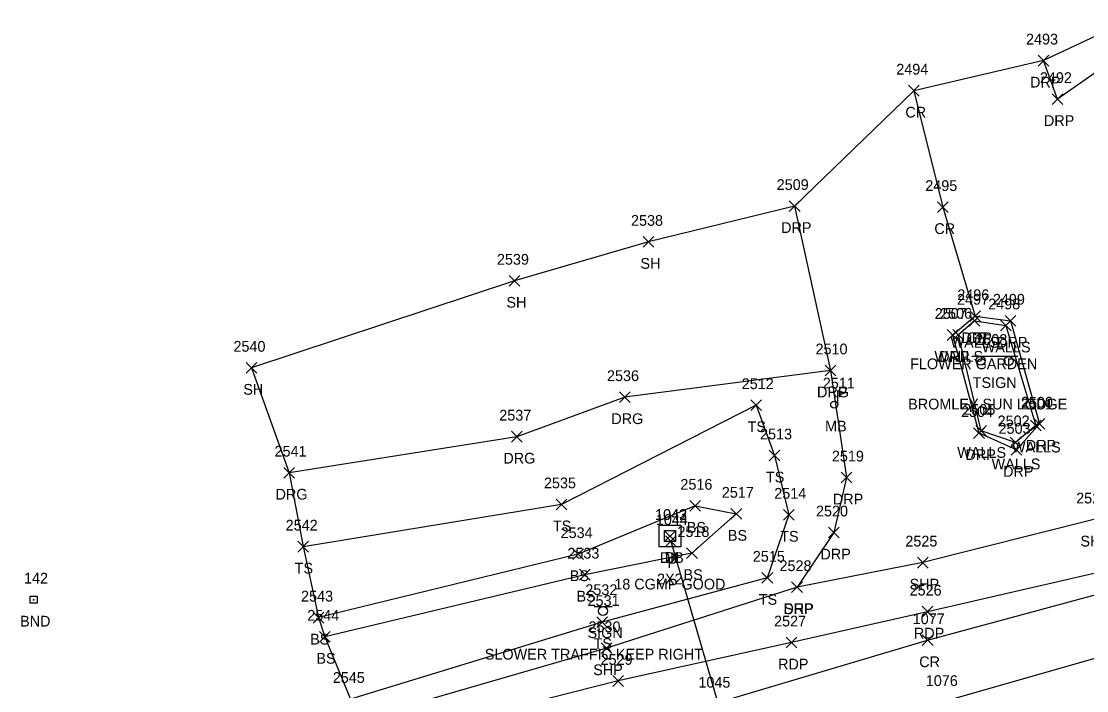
# Model space of a CAD drawing. Extents: x 49137 to 50946, y 9590 to 10709.
# Drawn here: x 49570.6 to 49768.6, y 9959 to 10083.5 of the extents above; entities that cross this region are included whole.
import ezdxf

# ---------------------------------------------------------------- set-up
doc = ezdxf.new("R2010")
doc.units = 0
for name, color, linetype in [('D_A', 7, 'Continuous'), ('D_C', 7, 'Continuous'), ('D_I', 7, 'Continuous'), ('D_TIC', 7, 'Continuous'), ('DCP', 7, 'Continuous'), ('DS', 7, 'Continuous'), ('L_A', 7, 'Continuous'), ('L_C', 7, 'Continuous'), ('L_I', 7, 'Continuous'), ('L_TIC', 7, 'Continuous'), ('LELB', 7, 'Continuous'), ('LMB', 7, 'Continuous'), ('LSOGP', 7, 'Continuous'), ('LWS', 7, 'Continuous'), ('M_A', 7, 'Continuous'), ('M_I', 7, 'Continuous'), ('MHBP', 7, 'Continuous'), ('P_A', 7, 'Continuous'), ('P_I', 7, 'Continuous'), ('P_TIC', 7, 'Continuous'), ('PET', 7, 'Continuous'), ('PRC', 7, 'Continuous'), ('PSP', 7, 'Continuous'), ('R_A', 7, 'Continuous'), ('R_I', 7, 'Continuous'), ('R_TIC', 7, 'Continuous'), ('RDG', 7, 'Continuous'), ('RDP', 7, 'Continuous'), ('S_A', 7, 'Continuous'), ('S_C', 7, 'Continuous'), ('S_I', 7, 'Continuous'), ('SSGN', 7, 'Continuous')]:
    doc.layers.add(name, color=color, linetype=linetype)

msp = doc.modelspace()

# ---------------------------------------------------------------- linework, layer by layer
at = {"layer": 'D_TIC'}
for points in [[(49690.14, 9986.76), (49692.14, 9988.76)], [(49692.14, 9986.76), (49690.14, 9988.76)], [(49690.29, 9985.82), (49692.29, 9987.82)], [(49692.29, 9985.82), (49690.29, 9987.82)]]:
    msp.add_lwpolyline(points, dxfattribs=at)
at = {"layer": 'DCP'}
msp.add_lwpolyline([(49691.29, 9986.82), (49735.05, 9836.12)], dxfattribs=at)
at = {"layer": 'DS'}
for p, q in [((49689.15, 9989.77), (49693.15, 9989.77)), ((49689.15, 9985.77), (49689.15, 9989.77)), ((49690.15, 9986.77), (49690.15, 9988.77)), ((49690.15, 9988.77), (49692.15, 9988.77)), ((49692.15, 9988.77), (49692.15, 9986.77)), ((49693.15, 9989.77), (49693.15, 9985.77)), ((49692.15, 9986.77), (49690.15, 9986.77)), ((49691.16, 9987.77), (49691.16, 9987.77)), ((49691.16, 9987.77), (49691.16, 9987.77)), ((49693.15, 9985.77), (49689.15, 9985.77))]:
    msp.add_line(p, q, dxfattribs=at)
at = {"layer": 'L_TIC'}
for points in [[(49686.16, 10041.48), (49688.16, 10043.48)], [(49688.16, 10041.48), (49686.16, 10043.48)], [(49661.24, 10034.24), (49663.24, 10036.24)], [(49663.24, 10034.24), (49661.24, 10036.24)], [(49746.76, 10026.8), (49748.76, 10028.8)], [(49748.76, 10026.8), (49746.76, 10028.8)], [(49746.76, 10026.8), (49748.76, 10028.8)], [(49748.76, 10026.8), (49746.76, 10028.8)], [(49752.56, 10025.93), (49754.56, 10027.93)], [(49754.56, 10025.93), (49752.56, 10027.93)], [(49743.75, 10024.19), (49745.75, 10026.19)], [(49745.75, 10024.19), (49743.75, 10026.19)], [(49743.75, 10024.19), (49745.75, 10026.19)], [(49745.75, 10024.19), (49743.75, 10026.19)], [(49612.33, 10018.05), (49614.33, 10020.05)], [(49614.33, 10018.05), (49612.33, 10020.05)], [(49706.17, 10011.1), (49708.17, 10013.1)], [(49708.17, 10011.1), (49706.17, 10013.1)], [(49706.17, 10011.1), (49708.17, 10013.1)], [(49708.17, 10011.1), (49706.17, 10013.1)], [(49748.01, 10006.31), (49750.01, 10008.31)], [(49750.01, 10006.31), (49748.01, 10008.31)], [(49758.16, 10007.31), (49760.16, 10009.31)], [(49760.16, 10007.31), (49758.16, 10009.31)], [(49754.39, 10004.18), (49756.39, 10006.18)], [(49756.39, 10004.18), (49754.39, 10006.18)], [(49709.58, 10001.74), (49711.58, 10003.74)], [(49711.58, 10001.74), (49709.58, 10003.74)], [(49669.97, 9992.64), (49671.97, 9994.64)], [(49671.97, 9992.64), (49669.97, 9994.64)], [(49694.83, 9992.38), (49696.83, 9994.38)], [(49696.83, 9992.38), (49694.83, 9994.38)], [(49694.83, 9992.38), (49696.83, 9994.38)], [(49696.83, 9992.38), (49694.83, 9994.38)], [(49702.47, 9990.89), (49704.47, 9992.89)], [(49704.47, 9990.89), (49702.47, 9992.89)], [(49712.22, 9990.71), (49714.22, 9992.71)], [(49714.22, 9990.71), (49712.22, 9992.71)], [(49621.96, 9984.78), (49623.96, 9986.78)], [(49623.96, 9984.78), (49621.96, 9986.78)], [(49673.07, 9983.38), (49675.07, 9985.38)], [(49675.07, 9983.38), (49673.07, 9985.38)], [(49694.23, 9983.58), (49696.23, 9985.58)], [(49696.23, 9983.58), (49694.23, 9985.58)], [(49674.33, 9979.57), (49676.33, 9981.57)], [(49676.33, 9979.57), (49674.33, 9981.57)], [(49708.24, 9978.98), (49710.24, 9980.98)], [(49710.24, 9978.98), (49708.24, 9980.98)], [(49624.82, 9971.58), (49626.82, 9973.58)], [(49626.82, 9971.58), (49624.82, 9973.58)], [(49677.52, 9970.76), (49679.52, 9972.76)], [(49679.52, 9970.76), (49677.52, 9972.76)], [(49625.97, 9968.01), (49627.97, 9970.01)], [(49627.97, 9968.01), (49625.97, 9970.01)]]:
    msp.add_lwpolyline(points, dxfattribs=at)
at = {"layer": 'LELB'}
for points in [[(49707.17, 10012.1), (49670.97, 9993.64), (49622.96, 9985.78)], [(49707.17, 10012.1), (49710.58, 10002.74), (49713.22, 9991.71), (49709.24, 9979.98), (49678.52, 9971.76), (49631.72, 9957.44)], [(49695.83, 9993.38), (49674.07, 9984.38), (49625.82, 9972.58)], [(49695.83, 9993.38), (49703.47, 9991.89), (49695.23, 9984.58), (49675.33, 9980.57), (49626.97, 9969.01)]]:
    msp.add_lwpolyline(points, dxfattribs=at)
at = {"layer": 'LMB'}
for p, q in [((49722.33, 10014.81), (49723.62, 10014.43)), ((49722.33, 10012.22), (49722.33, 10014.81)), ((49722.33, 10013.91), (49723.61, 10014.42)), ((49721.68, 10012.21), (49721.68, 10012.21))]:
    msp.add_line(p, q, dxfattribs=at)
msp.add_circle((49721.68, 10012.21), 0.656, dxfattribs=at)
at = {"layer": 'LSOGP'}
msp.add_lwpolyline([(49776.2, 10083.52), (49760.59, 10076.2), (49736.46, 10070.61), (49714.32, 10049.15), (49687.16, 10042.49), (49662.24, 10035.25), (49613.34, 10019.05), (49620.33, 9999.55), (49622.96, 9985.79), (49625.81, 9972.58), (49626.96, 9969.01), (49631.72, 9957.44)], dxfattribs=at)
at = {"layer": 'LWS'}
for points in [[(49747.76, 10027.8), (49753.56, 10026.93), (49759.16, 10008.31), (49755.39, 10005.18), (49749.01, 10007.31), (49744.75, 10025.19)], [(49747.76, 10027.8), (49744.75, 10025.19)]]:
    msp.add_lwpolyline(points, dxfattribs=at)
at = {"layer": 'MHBP'}
msp.add_lwpolyline([(49572.22, 9976.55), (49573.47, 9976.55), (49573.47, 9975.3), (49572.22, 9975.3)], close=True, dxfattribs=at)
msp.add_circle((49572.85, 9975.92), 0.0833, dxfattribs=at)
at = {"layer": 'P_TIC'}
for points in [[(49735.47, 10069.61), (49737.47, 10071.61)], [(49737.47, 10069.61), (49735.47, 10071.61)], [(49740.86, 10047.95), (49742.86, 10049.95)], [(49742.86, 10047.95), (49740.86, 10049.95)], [(49746.87, 10027.65), (49748.87, 10029.65)], [(49748.87, 10027.65), (49746.87, 10029.65)], [(49737.16, 9981.81), (49739.16, 9983.81)], [(49739.16, 9981.81), (49737.16, 9983.81)], [(49713.76, 9977.24), (49715.76, 9979.24)], [(49715.76, 9977.24), (49713.76, 9979.24)], [(49738, 9972.69), (49740, 9974.69)], [(49740, 9972.69), (49738, 9974.69)], [(49712.75, 9966.94), (49714.75, 9968.94)], [(49714.75, 9966.94), (49712.75, 9968.94)], [(49738.04, 9967.37), (49740.04, 9969.37)], [(49740.04, 9967.37), (49738.04, 9969.37)], [(49678.34, 9965.88), (49680.34, 9967.88)], [(49680.34, 9965.88), (49678.34, 9967.88)], [(49680.51, 9959.8), (49682.51, 9961.8)], [(49682.51, 9959.8), (49680.51, 9961.8)]]:
    msp.add_lwpolyline(points, dxfattribs=at)
at = {"layer": 'PET'}
msp.add_lwpolyline([(49773.46, 9981.58), (49739, 9973.69), (49713.75, 9967.94), (49681.51, 9960.8), (49634.84, 9948.96)], dxfattribs=at)
at = {"layer": 'PRC'}
for points in [[(49736.47, 10070.61), (49741.86, 10048.95), (49747.87, 10028.65)], [(49635.51, 9938.51), (49665.25, 9946.57), (49699.21, 9956.56), (49739.04, 9968.37), (49782.75, 9980.26), (49832.37, 9994.06), (49891.41, 10012.39)], [(49638.31, 9927.11), (49668.24, 9935.56), (49702.01, 9945.71), (49741.53, 9956.86), (49785.57, 9969.42)]]:
    msp.add_lwpolyline(points, dxfattribs=at)
at = {"layer": 'PSP'}
msp.add_lwpolyline([(49769.91, 9990.82), (49738.16, 9982.81), (49714.76, 9978.24), (49679.34, 9966.88), (49632.26, 9953.25)], dxfattribs=at)
at = {"layer": 'R_TIC'}
for points in [[(49759.59, 10075.2), (49761.59, 10077.2)], [(49761.59, 10075.2), (49759.59, 10077.2)], [(49762.17, 10068.04), (49764.17, 10070.04)], [(49764.17, 10068.04), (49762.17, 10070.04)], [(49713.32, 10048.14), (49715.32, 10050.14)], [(49715.32, 10048.14), (49713.32, 10050.14)], [(49746.87, 10027.65), (49748.87, 10029.65)], [(49748.87, 10027.65), (49746.87, 10029.65)], [(49746.87, 10027.65), (49748.87, 10029.65)], [(49748.87, 10027.65), (49746.87, 10029.65)], [(49753.44, 10026.81), (49755.44, 10028.81)], [(49755.44, 10026.81), (49753.44, 10028.81)], [(49742.7, 10024.16), (49744.7, 10026.16)], [(49744.7, 10024.16), (49742.7, 10026.16)], [(49742.7, 10024.16), (49744.7, 10026.16)], [(49744.7, 10024.16), (49742.7, 10026.16)], [(49719.98, 10017.56), (49721.98, 10019.56)], [(49721.98, 10017.56), (49719.98, 10019.56)], [(49719.98, 10017.56), (49721.98, 10019.56)], [(49721.98, 10017.56), (49719.98, 10019.56)], [(49681.75, 10012.59), (49683.75, 10014.59)], [(49683.75, 10012.59), (49681.75, 10014.59)], [(49747.59, 10005.91), (49749.59, 10007.91)], [(49749.59, 10005.91), (49747.59, 10007.91)], [(49758.81, 10007.65), (49760.81, 10009.65)], [(49760.81, 10007.65), (49758.81, 10009.65)], [(49661.67, 10005.24), (49663.67, 10007.24)], [(49663.67, 10005.24), (49661.67, 10007.24)], [(49754.57, 10002.78), (49756.57, 10004.78)], [(49756.57, 10002.78), (49754.57, 10004.78)], [(49619.33, 9998.54), (49621.33, 10000.54)], [(49621.33, 9998.54), (49619.33, 10000.54)], [(49722.94, 9997.63), (49724.94, 9999.63)], [(49724.94, 9997.63), (49722.94, 9999.63)], [(49720.62, 9987.41), (49722.62, 9989.41)], [(49722.62, 9987.41), (49720.62, 9989.41)], [(49713.76, 9977.24), (49715.76, 9979.24)], [(49715.76, 9977.24), (49713.76, 9979.24)]]:
    msp.add_lwpolyline(points, dxfattribs=at)
at = {"layer": 'RDG'}
msp.add_lwpolyline([(49720.98, 10018.56), (49682.75, 10013.59), (49662.67, 10006.24), (49620.33, 9999.54)], dxfattribs=at)
at = {"layer": 'RDP'}
for points in [[(49776.21, 10083.52), (49771.42, 10074.83), (49763.17, 10069.04), (49760.59, 10076.2)], [(49714.32, 10049.14), (49720.98, 10018.56), (49723.94, 9998.63), (49721.62, 9988.41), (49714.76, 9978.24)], [(49747.87, 10028.65), (49754.44, 10027.81), (49759.81, 10008.65), (49755.57, 10003.78), (49748.59, 10006.91), (49743.7, 10025.16)], [(49747.87, 10028.65), (49743.7, 10025.16)]]:
    msp.add_lwpolyline(points, dxfattribs=at)
at = {"layer": 'SSGN'}
for p, q in [((49747.23, 10021.23), (49755.82, 10021.23)), ((49751.25, 10020.33), (49751.25, 10020.33)), ((49677.04, 9974.64), (49680.37, 9974.64)), ((49678.69, 9973.81), (49678.69, 9973.81))]:
    msp.add_line(p, q, dxfattribs=at)
for centre in [(49748.89, 10020.4), (49754.1, 10020.33), (49678.69, 9973.81)]:
    msp.add_circle(centre, 0.833, dxfattribs=at)

# ---------------------------------------------------------------- texts
at = {"layer": 'D_A'}
for s, p in [('DIB', (49689.24, 9982.76)), ('DI', (49690.21, 9982.77)), ('P', (49690.66, 9981.82))]:
    msp.add_text(s, height=2, dxfattribs=at).set_placement(p)
at = {"layer": 'D_C'}
for s, p in [('2X2', (49688.73, 9978.77)), ('18 CGMP GOOD', (49680.79, 9977.82))]:
    msp.add_text(s, height=2, dxfattribs=at).set_placement(p)
at = {"layer": 'D_I'}
for s, p in [('1043', (49688.36, 9990.76)), ('1042', (49688.39, 9990.77)), ('1044', (49688.51, 9989.82))]:
    msp.add_text(s, height=2, dxfattribs=at).set_placement(p)
at = {"layer": 'L_A'}
for s, p in [('SH', (49685.65, 10037.48)), ('SH', (49660.73, 10030.24)), ('WALLS', (49743.3, 10022.8)), ('WALLS', (49743.3, 10022.8)), ('WALLS', (49749.11, 10021.93)), ('WALLS', (49740.3, 10020.19)), ('WALLS', (49740.3, 10020.19)), ('SH', (49611.82, 10014.05)), ('TS', (49705.58, 10007.1)), ('TS', (49705.58, 10007.1)), ('MB', (49719.98, 10007.21)), ('WALLS', (49744.55, 10002.31)), ('WALLS', (49754.71, 10003.31)), ('WALLS', (49750.93, 10000.18)), ('TS', (49708.99, 9997.74)), ('TS', (49669.38, 9988.64)), ('BS', (49694.27, 9988.38)), ('BS', (49694.27, 9988.38)), ('BS', (49701.91, 9986.89)), ('TS', (49711.63, 9986.71)), ('TS', (49621.37, 9980.78)), ('BS', (49672.51, 9979.38)), ('BS', (49693.67, 9979.58)), ('BS', (49673.77, 9975.57)), ('TS', (49707.65, 9974.98)), ('BS', (49624.26, 9967.58)), ('TS', (49676.93, 9966.76)), ('BS', (49625.41, 9964.01))]:
    msp.add_text(s, height=2, dxfattribs=at).set_placement(p)
at = {"layer": 'L_C'}
msp.add_text('FLOWER GARDEN', height=2, dxfattribs=at).set_placement((49735.79, 10018.8))
msp.add_text('FLOWER GARDEN', height=2, dxfattribs=at).set_placement((49735.79, 10018.8))
at = {"layer": 'L_I'}
for s, p in [('2538', (49683.9, 10045.48)), ('2539', (49658.97, 10038.24)), ('2497', (49744.5, 10030.8)), ('2497', (49744.5, 10030.8)), ('2498', (49750.3, 10029.93)), ('2506', (49741.36, 10028.19)), ('2506', (49741.36, 10028.19)), ('2540', (49609.99, 10022.05)), ('2512', (49704.48, 10015.1)), ('2512', (49704.48, 10015.1)), ('2511', (49719.55, 10015.21)), ('2505', (49745.67, 10010.31)), ('2501', (49756.39, 10011.31)), ('2502', (49752.05, 10008.18)), ('2513', (49707.89, 10005.74)), ('2535', (49667.71, 9996.64)), ('2516', (49693.08, 9996.38)), ('2516', (49693.08, 9996.38)), ('2517', (49700.78, 9994.89)), ('2514', (49710.53, 9994.71)), ('2542', (49619.7, 9988.78)), ('2534', (49670.81, 9987.38)), ('2518', (49692.53, 9987.58)), ('2533', (49672.07, 9983.57)), ('2515', (49706.54, 9982.98)), ('2543', (49622.56, 9975.58)), ('2531', (49675.82, 9974.76)), ('2544', (49623.71, 9972.01)), ('2545', (49628.46, 9960.44))]:
    msp.add_text(s, height=2, dxfattribs=at).set_placement(p)
at = {"layer": 'M_A'}
msp.add_text('BND', height=2, dxfattribs=at).set_placement((49570.33, 9970.92))
at = {"layer": 'M_I'}
msp.add_text('142', height=2, dxfattribs=at).set_placement((49571.05, 9978.92))
at = {"layer": 'P_A'}
for s, p in [('CR', (49734.9, 10065.61)), ('CR', (49740.29, 10043.95)), ('CR', (49746.3, 10023.65)), ('SHP', (49767.44, 9985.82)), ('SHP', (49735.69, 9977.81)), ('SHP', (49712.29, 9973.24)), ('RDP', (49736.49, 9968.69)), ('RDP', (49711.23, 9962.94)), ('CR', (49737.48, 9963.37)), ('SHP', (49676.87, 9961.88))]:
    msp.add_text(s, height=2, dxfattribs=at).set_placement(p)
at = {"layer": 'P_I'}
for s, p in [('2494', (49733.21, 10073.61)), ('2495', (49738.6, 10051.95)), ('2496', (49744.55, 10031.65)), ('2524', (49766.65, 9993.82)), ('2525', (49734.9, 9985.81)), ('2528', (49711.5, 9981.24)), ('2526', (49735.69, 9976.69)), ('2527', (49710.49, 9970.94)), ('1077', (49736.27, 9971.37)), ('2530', (49675.99, 9969.88)), ('2529', (49678.24, 9963.8)), ('1045', (49696.43, 9959.56)), ('1076', (49738.7, 9959.86))]:
    msp.add_text(s, height=2, dxfattribs=at).set_placement(p)
at = {"layer": 'R_A'}
for s, p in [('DRP', (49758.08, 10071.2)), ('DRP', (49760.66, 10064.04)), ('DRP', (49711.81, 10044.14)), ('DRP', (49745.35, 10023.65)), ('DRP', (49745.35, 10023.65)), ('DRP', (49751.93, 10022.81)), ('DRP', (49741.19, 10020.16)), ('DRP', (49741.19, 10020.16)), ('DRG', (49718.47, 10013.56)), ('DRP', (49718.47, 10013.56)), ('DRG', (49680.23, 10008.59)), ('DRP', (49746.08, 10001.91)), ('DRP', (49757.29, 10003.65)), ('DRG', (49660.16, 10001.24)), ('DRP', (49753.06, 9998.78)), ('DRG', (49617.82, 9994.54)), ('DRP', (49721.43, 9993.63)), ('DRP', (49719.11, 9983.41)), ('DRP', (49712.24, 9973.24))]:
    msp.add_text(s, height=2, dxfattribs=at).set_placement(p)
at = {"layer": 'R_I'}
for s, p in [('2493', (49757.33, 10079.2)), ('2492', (49759.91, 10072.04)), ('2509', (49710.98, 10052.14)), ('2496', (49744.55, 10031.65)), ('2496', (49744.55, 10031.65)), ('2499', (49751.17, 10030.81)), ('2507', (49740.36, 10028.16)), ('2507', (49740.36, 10028.16)), ('2510', (49718.2, 10021.56)), ('2510', (49718.2, 10021.56)), ('2536', (49679.43, 10016.59)), ('2504', (49745.26, 10009.91)), ('2500', (49756.38, 10011.65)), ('2537', (49659.41, 10009.24)), ('2503', (49752.23, 10006.78)), ('2541', (49617.63, 10002.54)), ('2519', (49721.24, 10001.63)), ('2520', (49718.28, 9991.41)), ('2528', (49711.5, 9981.24))]:
    msp.add_text(s, height=2, dxfattribs=at).set_placement(p)
at = {"layer": 'S_A'}
for s, p in [('TSIGN', (49747.42, 10015.31)), ('SIGN', (49675.82, 9968.78))]:
    msp.add_text(s, height=2, dxfattribs=at).set_placement(p)
at = {"layer": 'S_C'}
for s, p in [('BROMLEY SUN LODGE', (49735.42, 10011.31)), ('SLOWER TRAFFIC KEEP RIGHT', (49656.72, 9964.78))]:
    msp.add_text(s, height=2, dxfattribs=at).set_placement(p)
at = {"layer": 'S_I'}
for s, p in [('2508', (49747.9, 10023.31)), ('2532', (49675.41, 9976.78))]:
    msp.add_text(s, height=2, dxfattribs=at).set_placement(p)

doc.saveas('drawing.dxf')
